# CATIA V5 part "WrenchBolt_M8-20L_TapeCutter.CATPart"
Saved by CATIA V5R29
Part number: WrenchBolt_M8-20L_TapeCutter
Source: Unknown
Bounding box of the stored display mesh (mm): x -6.635 to 6.635, y -6.635 to 6.625, z -20 to 8
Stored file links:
  C:\가치같이\SmartFactory_BoxErectorConveyor\Boxing(under)\WrenchBolt_M8-20L_TapeCutter.CATPart
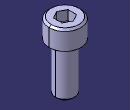
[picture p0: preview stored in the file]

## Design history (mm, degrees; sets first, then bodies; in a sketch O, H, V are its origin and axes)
Body1 (main body)
  Solid1 "PartBody": solid without history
